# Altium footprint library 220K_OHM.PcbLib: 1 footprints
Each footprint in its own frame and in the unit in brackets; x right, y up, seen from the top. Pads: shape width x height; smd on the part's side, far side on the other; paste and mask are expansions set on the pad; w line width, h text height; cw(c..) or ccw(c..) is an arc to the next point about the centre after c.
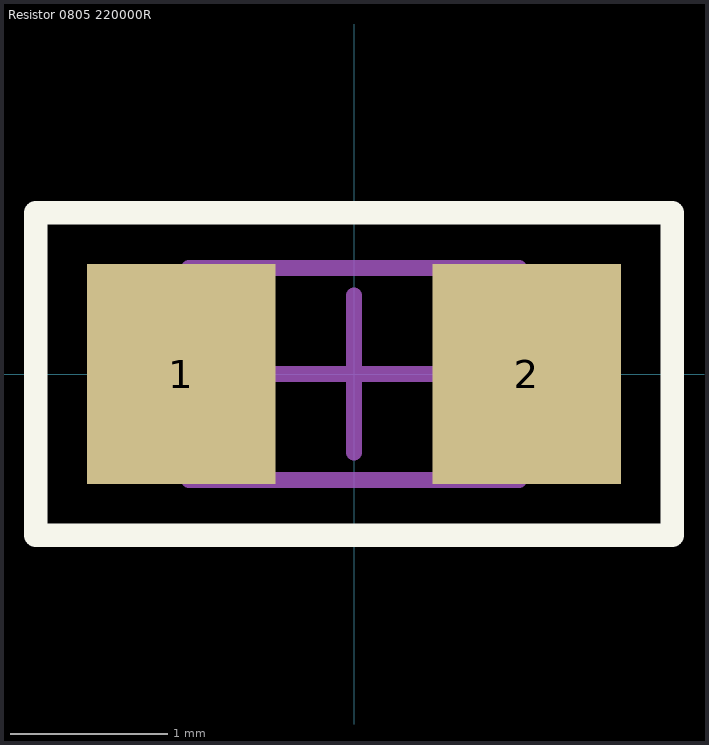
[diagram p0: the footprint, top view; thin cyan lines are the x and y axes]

## Resistor 0805 220000R [mm]
pads (2):
  rect 1.2x1.4 smd: 1(-1.1,0) 2(1.1,0)
Top Overlay:
  lines w0.15: -2.025,-1.025 -2.025,1.025 2.025,1.025 2.025,-1.025 -2.025,-1.025
Mechanical 13:
  lines w0.1: -1.05,-0.675 -1.05,0.675 1.05,0.675 1.05,-0.675 -1.05,-0.675
Mechanical 15:
  lines w0.1: -0.5,0 0.5,0 ; 0,-0.5 0,0.5
3D body "Res 0805 220000R.step": height 0.51, standoff 0, extent -1,-0.625 1,0.625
